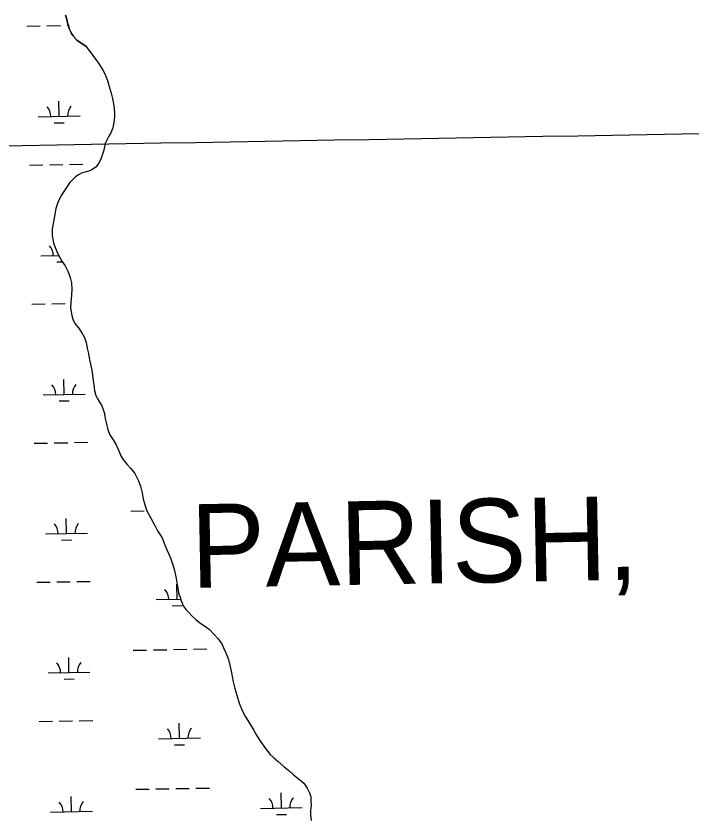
# Model space of a CAD drawing. Extents: x 3903937 to 3942190, y 260677 to 286651.
# Drawn here: x 3915954 to 3917570, y 276665 to 278583 of the extents above; entities that cross this region are included whole.
import ezdxf

# ---------------------------------------------------------------- set-up
doc = ezdxf.new("R2010")
doc.units = 0
for name, color, linetype in [('V-GRID-MAJR', 7, 'Continuous'), ('V-TOPO-GNAM-IDEN', 7, 'Continuous'), ('V-TOPO-SHOR', 7, 'Continuous'), ('V-WETL-SWMP', 7, 'Continuous')]:
    doc.layers.add(name, color=color, linetype=linetype)

msp = doc.modelspace()

# ---------------------------------------------------------------- linework, layer by layer
at = {"layer": 'V-GRID-MAJR'}
msp.add_spline([(3907996.24, 278136.142), (3913310.651, 278227.748), (3918625.049, 278320.127), (3923939.434, 278413.279), (3929253.805, 278507.203), (3934568.162, 278601.901), (3939882.505, 278697.37200000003), (3939882.506, 278697.37200000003)], degree=3, dxfattribs=at)
at = {"layer": 'V-TOPO-SHOR'}
for points in [[(3916121.0300000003, 278510.66000000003), (3916098.768, 278525.893), (3916095.019, 278529.926), (3916093.075, 278532.551), (3916090.083, 278536.266), (3916086.3540000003, 278541.67100000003), (3916083.544, 278547.213), (3916081.045, 278553.21), (3916078.717, 278560.271), (3916077.269, 278565.029), (3916075.835, 278570.853), (3916073.971, 278578.214), (3916071.952, 278585.574)], [(3916121.0300000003, 278510.66000000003), (3916151.115, 278470.827), (3916162.9450000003, 278451.279), (3916167.4560000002, 278441.29), (3916171.9930000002, 278428.896), (3916176.5470000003, 278414.492), (3916181.119, 278398.487), (3916184.049, 278386.074), (3916186.583, 278373.25800000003), (3916188.301, 278361.64), (3916189.204, 278351.213), (3916189.3000000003, 278341.58400000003), (3916187.816, 278329.13), (3916184.731, 278316.25800000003), (3916180.035, 278304.175), (3916175.704, 278295.704), (3916167.045, 278278.364), (3916163.592, 278262.279), (3916159.696, 278250.202), (3916156.1720000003, 278241.34), (3916150.6610000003, 278230.451), (3916145.1210000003, 278222.37200000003), (3916135.157, 278215.451), (3916127.967, 278212.17), (3916119.162, 278209.676), (3916111.9560000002, 278208.001), (3916103.1720000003, 278203.501), (3916095.594, 278198.613), (3916082.487, 278184.84), (3916072.593, 278170.69800000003), (3916061.519, 278154.136), (3916053.659, 278137.206), (3916048.986, 278122.714), (3916045.5470000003, 278105.023), (3916042.5100000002, 278087.337), (3916040.241, 278073.26900000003), (3916040.392, 278057.62), (3916042.96, 278041.193), (3916047.083, 278029.999), (3916053.653, 278014.813), (3916063.457, 277997.253), (3916071.188, 277986.092), (3916077.3340000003, 277973.31), (3916083.103, 277957.719), (3916086.038, 277944.904), (3916086.995, 277929.266), (3916086.321, 277916.015), (3916084.48, 277899.14400000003), (3916083.812, 277885.494), (3916087.205, 277866.667), (3916089.6920000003, 277858.665), (3916094.609, 277848.28), (3916103.1410000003, 277837.528), (3916111.284, 277825.57), (3916117.0100000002, 277814.39), (3916121.139, 277802.792), (3916124.08, 277789.177), (3916127.015, 277776.364), (3916129.5700000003, 277761.142), (3916131.68, 277750.727), (3916134.629, 277736.31200000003), (3916141.123, 277687.819), (3916144.455, 277675.412), (3916147.327, 277669.018), (3916153.034, 277659.84500000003), (3916157.9250000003, 277652.27), (3916162.039, 277641.876), (3916164.937, 277632.675), (3916165.822, 277624.255), (3916168.757, 277611.445), (3916172.943, 277593.828), (3916177.875, 277581.837), (3916185.616, 277569.875), (3916192.96, 277557.507), (3916199.522, 277543.126), (3916204.0500000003, 277531.532), (3916210.573, 277521.163), (3916219.105, 277510.411), (3916228.026, 277500.867), (3916237.3710000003, 277488.92100000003), (3916245.952, 277473.354), (3916250.912, 277458.556), (3916255.08, 277442.544), (3916257.22, 277428.92100000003), (3916261.376, 277414.515), (3916266.733, 277400.12200000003), (3916274.919, 277383.75), (3916285.134, 277364.989), (3916292.085, 277351.816), (3916303.079, 277335.471), (3916310.491, 277316.281), (3916315.019, 277304.68700000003), (3916323.213, 277287.513), (3916328.188, 277271.108), (3916332.339, 277257.104), (3916336.134, 277238.281), (3916339.089, 277223.462), (3916342.927, 277200.225), (3916345.806, 277193.03), (3916348.698, 277184.632), (3916354.035, 277172.243)], [(3916354.035, 277172.243), (3916359.733, 277164.27400000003), (3916365.8170000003, 277157.512), (3916374.7430000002, 277147.567), (3916383.645, 277140.03), (3916392.951, 277132.094), (3916406.681, 277123.4), (3916416.381, 277116.273), (3916426.924, 277105.14), (3916436.664, 277093.999), (3916445.614, 277081.648), (3916450.537, 277070.46), (3916455.055, 277060.07), (3916461.23, 277044.079), (3916464.969, 277030.874), (3916467.9250000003, 277016.055), (3916472.987, 276990.82300000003), (3916476.3540000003, 276974.806), (3916481.327, 276958.803), (3916487.133, 276939.597), (3916494.127, 276922.00800000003), (3916502.3000000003, 276906.841), (3916511.674, 276892.085), (3916521.461, 276876.129), (3916529.627, 276861.762), (3916538.187, 276848.202), (3916549.992, 276831.063), (3916561.365, 276817.128), (3916569.464, 276809.583), (3916579.987, 276800.457), (3916594.96, 276787.762), (3916605.481, 276778.636), (3916617.22, 276768.316), (3916632.18, 276756.827), (3916641.8880000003, 276748.897), (3916649.629, 276736.933), (3916655.362, 276725.351), (3916658.2600000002, 276716.15), (3916658.7630000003, 276705.721), (3916658.858, 276696.091), (3916657.7800000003, 276683.24), (3916657.481, 276672.804), (3916659.218, 276659.176)]]:
    msp.add_lwpolyline(points, dxfattribs=at)
at = {"layer": 'V-WETL-SWMP'}
for p, q in [((3916071.953, 278585.5749999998), (3916073.971, 278578.21299999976)), ((3916073.971, 278578.21299999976), (3916075.836, 278570.85299999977)), ((3916075.836, 278570.85299999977), (3916077.268, 278565.028)), ((3916077.268, 278565.028), (3916078.717, 278560.2709999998)), ((3915979.6389084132, 278559.3697548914), (3916011.63395243, 278559.93292306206)), ((3916027.6314744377, 278560.2145071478), (3916059.6265184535, 278560.7776753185)), ((3916075.624040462, 278561.0592594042), (3916078.4616790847, 278561.1092067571)), ((3916078.717, 278560.2709999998), (3916081.045, 278553.20900000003)), ((3916081.045, 278553.20900000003), (3916083.543, 278547.213)), ((3916083.543, 278547.213), (3916086.353, 278541.67100000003)), ((3916086.353, 278541.67100000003), (3916090.082, 278536.266)), ((3916090.082, 278536.26599999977), (3916093.076, 278532.552)), ((3916093.076, 278532.552), (3916095.018, 278529.92499999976)), ((3916095.018, 278529.92499999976), (3916098.769, 278525.89399999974)), ((3916098.769, 278525.89399999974), (3916121.031, 278510.66000000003)), ((3916121.031, 278510.66000000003), (3916151.116, 278470.826)), ((3916151.116, 278470.826), (3916162.9450000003, 278451.27799999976)), ((3916162.9450000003, 278451.27799999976), (3916167.457, 278441.29)), ((3916167.457, 278441.29), (3916171.992, 278428.895)), ((3916171.992, 278428.895), (3916176.5470000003, 278414.4929999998)), ((3916176.5470000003, 278414.4929999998), (3916181.1180000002, 278398.487)), ((3916181.1180000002, 278398.487), (3916184.049, 278386.0749999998)), ((3916056.8588001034, 278343.4523080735), (3916056.2252359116, 278379.4467325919)), ((3916184.049, 278386.0749999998), (3916186.582, 278373.259)), ((3916186.582, 278373.259), (3916188.301, 278361.639)), ((3916188.301, 278361.639), (3916189.205, 278351.214)), ((3916006.866543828, 278342.57235780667), (3916106.8510563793, 278344.3322583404)), ((3916189.3000000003, 278341.58400000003), (3916187.816, 278329.13)), ((3916189.205, 278351.214), (3916189.3000000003, 278341.58400000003)), ((3916045.1322288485, 278327.81250987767), (3916069.128511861, 278328.2348860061)), ((3916184.7320000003, 278316.25800000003), (3916180.035, 278304.174)), ((3916187.816, 278329.13), (3916184.7320000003, 278316.25800000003)), ((3916175.704, 278295.704), (3916167.045, 278278.36399999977)), ((3916180.035, 278304.174), (3916175.704, 278295.704)), ((3916167.045, 278278.36399999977), (3916163.591, 278262.279)), ((3916163.591, 278262.279), (3916159.696, 278250.202)), ((3916156.171, 278241.34), (3916150.66, 278230.451)), ((3916159.696, 278250.202), (3916156.171, 278241.34)), ((3915985.4936575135, 278226.7462777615), (3916017.4887015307, 278227.30944593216)), ((3916033.4862235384, 278227.5910300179), (3916065.4812675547, 278228.15419818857)), ((3916081.4787895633, 278228.43578227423), (3916113.473833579, 278228.9989504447)), ((3916145.1210000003, 278222.371), (3916135.157, 278215.45199999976)), ((3916150.66, 278230.451), (3916145.1210000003, 278222.371)), ((3916103.171, 278203.501), (3916095.594, 278198.6119999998)), ((3916111.955, 278208.00099999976), (3916103.171, 278203.501)), ((3916119.162, 278209.677), (3916111.955, 278208.00099999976)), ((3916127.966, 278212.17099999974), (3916119.162, 278209.677)), ((3916135.157, 278215.45199999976), (3916127.966, 278212.17099999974)), ((3916082.486, 278184.8399999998), (3916072.593, 278170.69800000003)), ((3916095.594, 278198.6119999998), (3916082.486, 278184.8399999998)), ((3916072.593, 278170.69800000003), (3916061.519, 278154.137)), ((3916061.519, 278154.137), (3916053.659, 278137.206)), ((3916053.659, 278137.206), (3916048.985, 278122.714)), ((3916045.5470000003, 278105.023), (3916042.5100000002, 278087.33699999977)), ((3916048.985, 278122.714), (3916045.5470000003, 278105.023)), ((3916042.5100000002, 278087.33699999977), (3916040.24, 278073.27)), ((3916040.24, 278073.27), (3916040.393, 278057.621)), ((3916040.393, 278057.621), (3916042.961, 278041.1939999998)), ((3916042.961, 278041.1939999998), (3916047.0840000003, 278029.998)), ((3916047.0840000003, 278029.998), (3916053.653, 278014.813)), ((3916012.721292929, 278009.94888067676), (3916055.943714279, 278010.70967012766)), ((3916053.653, 278014.813), (3916063.4560000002, 277997.2529999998)), ((3916050.9869779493, 277995.18903274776), (3916064.7185744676, 277995.43073262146)), ((3916063.4560000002, 277997.2529999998), (3916071.1890000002, 277986.092)), ((3916071.1890000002, 277986.092), (3916077.3340000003, 277973.31099999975)), ((3916077.3340000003, 277973.31099999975), (3916083.1040000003, 277957.718)), ((3916083.1040000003, 277957.718), (3916086.039, 277944.9049999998)), ((3916086.039, 277944.9049999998), (3916086.994, 277929.2649999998)), ((3916086.321, 277916.016), (3916084.48, 277899.14400000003)), ((3916086.994, 277929.2649999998), (3916086.321, 277916.016)), ((3915991.3484066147, 277894.1228006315), (3916023.343450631, 277894.6859688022)), ((3916039.340972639, 277894.9675528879), (3916071.336016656, 277895.5307210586)), ((3916084.48, 277899.14400000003), (3916083.811, 277885.493)), ((3916083.811, 277885.493), (3916087.2060000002, 277866.666)), ((3916087.2060000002, 277866.666), (3916089.6920000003, 277858.66499999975)), ((3916089.6920000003, 277858.66499999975), (3916094.609, 277848.27899999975)), ((3916094.609, 277848.27899999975), (3916103.1410000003, 277837.528)), ((3916103.1410000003, 277837.528), (3916111.284, 277825.569)), ((3916111.284, 277825.569), (3916117.011, 277814.389)), ((3916117.011, 277814.389), (3916121.1380000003, 277802.792)), ((3916121.1380000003, 277802.792), (3916124.08, 277789.177)), ((3916124.08, 277789.177), (3916127.014, 277776.365)), ((3916127.014, 277776.365), (3916129.571, 277761.14099999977)), ((3916129.571, 277761.14099999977), (3916131.679, 277750.72799999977)), ((3916131.679, 277750.72799999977), (3916134.629, 277736.31099999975)), ((3916134.629, 277736.31099999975), (3916141.123, 277687.8189999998)), ((3916068.568298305, 277678.20535381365), (3916067.934734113, 277714.199778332)), ((3916141.123, 277687.8189999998), (3916144.455, 277675.4119999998)), ((3916018.5760420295, 277677.3254035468), (3916118.5605545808, 277679.0853040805)), ((3916056.8417270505, 277662.5655556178), (3916080.8380100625, 277662.98793174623)), ((3916144.455, 277675.4119999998), (3916147.327, 277669.01899999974)), ((3916147.327, 277669.01899999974), (3916153.034, 277659.84500000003)), ((3916153.034, 277659.84500000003), (3916157.924, 277652.26899999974)), ((3916157.924, 277652.26899999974), (3916162.039, 277641.87599999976)), ((3916162.039, 277641.87599999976), (3916164.938, 277632.675)), ((3916164.938, 277632.675), (3916165.823, 277624.256)), ((3916165.823, 277624.256), (3916168.757, 277611.4439999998)), ((3916168.757, 277611.4439999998), (3916172.9420000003, 277593.828)), ((3916172.9420000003, 277593.828), (3916177.875, 277581.83799999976)), ((3916177.875, 277581.83799999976), (3916185.617, 277569.875)), ((3916185.617, 277569.875), (3916192.961, 277557.507)), ((3915997.203155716, 277561.49932350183), (3916029.1981997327, 277562.0624916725)), ((3916045.195721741, 277562.34407575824), (3916077.1907657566, 277562.90724392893)), ((3916093.1882877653, 277563.1888280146), (3916125.1833317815, 277563.75199618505)), ((3916192.961, 277557.507), (3916199.522, 277543.12499999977)), ((3916199.522, 277543.12499999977), (3916204.0500000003, 277531.5319999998)), ((3916204.0500000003, 277531.5319999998), (3916210.572, 277521.1619999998)), ((3916210.572, 277521.1619999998), (3916219.1040000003, 277510.411)), ((3916219.1040000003, 277510.411), (3916228.026, 277500.868)), ((3916228.026, 277500.868), (3916237.372, 277488.92100000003)), ((3916237.372, 277488.92100000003), (3916245.952, 277473.354)), ((3916245.952, 277473.354), (3916250.912, 277458.555)), ((3916250.912, 277458.555), (3916255.0810000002, 277442.54499999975)), ((3916255.0810000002, 277442.54499999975), (3916257.221, 277428.9219999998)), ((3916257.221, 277428.9219999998), (3916261.375, 277414.516)), ((3916261.375, 277414.516), (3916266.733, 277400.12200000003)), ((3916228.098096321, 277399.03668347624), (3916260.093140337, 277399.5998516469)), ((3916266.733, 277400.12200000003), (3916274.919, 277383.74999999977)), ((3916074.423047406, 277345.581876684), (3916073.7894832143, 277381.5763012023)), ((3916274.919, 277383.74999999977), (3916285.134, 277364.98899999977)), ((3916285.134, 277364.98899999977), (3916292.085, 277351.815)), ((3916024.430791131, 277344.7019264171), (3916124.4153036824, 277346.4618269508)), ((3916292.085, 277351.815), (3916303.08, 277335.46999999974)), ((3916062.6964761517, 277329.9420784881), (3916086.692759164, 277330.36445461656)), ((3916303.08, 277335.46999999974), (3916310.491, 277316.281)), ((3916310.491, 277316.281), (3916315.018, 277304.688)), ((3916315.018, 277304.688), (3916323.2120000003, 277287.51299999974)), ((3916323.2120000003, 277287.51299999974), (3916328.188, 277271.109)), ((3916328.188, 277271.109), (3916332.338, 277257.10399999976)), ((3916332.338, 277257.10399999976), (3916336.134, 277238.281)), ((3916003.0579048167, 277228.87584637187), (3916035.0529488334, 277229.43901454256)), ((3916051.0504708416, 277229.7205986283), (3916083.045514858, 277230.28376679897)), ((3916099.0430368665, 277230.5653508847), (3916131.0380808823, 277231.12851905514)), ((3916336.134, 277238.281), (3916339.088, 277223.46199999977)), ((3916338.667167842, 277188.34595853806), (3916338.0336036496, 277224.34038305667)), ((3916339.088, 277223.46199999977), (3916342.927, 277200.22499999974)), ((3916288.674911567, 277187.466008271), (3916347.366303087, 277188.4990783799)), ((3916342.927, 277200.22499999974), (3916345.806, 277193.0299999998)), ((3916345.806, 277193.0299999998), (3916348.698, 277184.63199999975)), ((3916348.698, 277184.63199999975), (3916354.0360000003, 277172.244)), ((3916326.9405965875, 277172.7061603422), (3916350.936879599, 277173.1285364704)), ((3916354.0360000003, 277172.244), (3916359.7320000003, 277164.27400000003)), ((3916359.7320000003, 277164.27400000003), (3916365.8170000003, 277157.51199999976)), ((3916365.8170000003, 277157.51199999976), (3916374.7430000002, 277147.567)), ((3916374.7430000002, 277147.567), (3916383.645, 277140.03)), ((3916383.645, 277140.03), (3916392.952, 277132.09499999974)), ((3916392.952, 277132.09499999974), (3916406.681, 277123.401)), ((3916406.681, 277123.401), (3916416.381, 277116.27299999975)), ((3916416.381, 277116.27299999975), (3916426.924, 277105.1399999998)), ((3916426.924, 277105.14), (3916436.664, 277093.999)), ((3916436.664, 277093.999), (3916445.613, 277081.64699999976)), ((3916329.937977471, 277068.10271085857), (3916361.933021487, 277068.6658790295)), ((3916377.9305434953, 277068.947463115), (3916409.925587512, 277069.51063128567)), ((3916445.613, 277081.64699999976), (3916450.538, 277070.45899999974)), ((3916450.538, 277070.45899999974), (3916455.054, 277060.07)), ((3916080.277796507, 277012.958399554), (3916079.644232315, 277048.9528240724)), ((3916233.952845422, 277066.4132063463), (3916265.947889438, 277066.97637451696)), ((3916281.9454114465, 277067.2579586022), (3916313.9404554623, 277067.8211267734)), ((3916455.054, 277060.07), (3916461.23, 277044.0789999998)), ((3916461.23, 277044.0789999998), (3916464.97, 277030.873)), ((3916464.97, 277030.873), (3916467.924, 277016.054)), ((3916030.285540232, 277012.07844928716), (3916130.270052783, 277013.8383498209)), ((3916467.924, 277016.054), (3916472.987, 276990.82300000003)), ((3916068.5512252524, 276997.31860135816), (3916092.5475082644, 276997.7409774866)), ((3916472.987, 276990.82300000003), (3916476.3540000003, 276974.80499999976)), ((3916476.3540000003, 276974.80499999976), (3916481.326, 276958.802)), ((3916481.326, 276958.802), (3916487.132, 276939.597)), ((3916487.132, 276939.597), (3916494.126, 276922.009)), ((3916494.126, 276922.009), (3916502.3000000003, 276906.8399999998)), ((3916008.912653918, 276896.25236924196), (3916040.907697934, 276896.81553741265)), ((3916056.9052199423, 276897.0971214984), (3916088.900263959, 276897.66028966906)), ((3916104.8977859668, 276897.9418737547), (3916136.8928299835, 276898.5050419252)), ((3916502.3000000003, 276906.8399999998), (3916511.674, 276892.08399999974)), ((3916344.5219169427, 276855.7224814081), (3916343.888352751, 276891.7169059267)), ((3916511.674, 276892.08399999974), (3916521.461, 276876.1279999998)), ((3916521.461, 276876.1279999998), (3916529.627, 276861.76199999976)), ((3916529.627, 276861.76199999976), (3916538.187, 276848.20199999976)), ((3916294.5296606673, 276854.84253114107), (3916394.514173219, 276856.6024316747)), ((3916332.795345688, 276840.0826832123), (3916356.7916287, 276840.5050593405)), ((3916538.187, 276848.202), (3916549.992, 276831.06199999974)), ((3916549.992, 276831.06199999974), (3916561.365, 276817.129)), ((3916561.365, 276817.129), (3916569.464, 276809.583)), ((3916569.464, 276809.583), (3916579.987, 276800.457)), ((3916579.987, 276800.457), (3916594.9590000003, 276787.762)), ((3916594.9590000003, 276787.762), (3916605.481, 276778.63599999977)), ((3916605.481, 276778.63599999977), (3916617.22, 276768.31699999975)), ((3916617.22, 276768.31699999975), (3916632.18, 276756.82599999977)), ((3916632.18, 276756.82599999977), (3916641.8880000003, 276748.8959999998)), ((3916641.8880000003, 276748.896), (3916649.63, 276736.9329999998)), ((3916239.8075945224, 276733.78972921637), (3916271.802638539, 276734.35289738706)), ((3916287.8001605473, 276734.63448147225), (3916319.7952045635, 276735.1976496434)), ((3916335.792726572, 276735.47923372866), (3916367.787770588, 276736.0424018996)), ((3916383.7852925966, 276736.3239859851), (3916415.780336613, 276736.88715415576)), ((3916587.9628128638, 276689.16800399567), (3916587.3292486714, 276725.162428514)), ((3916649.63, 276736.9329999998), (3916655.361, 276725.3519999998)), ((3916655.361, 276725.3519999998), (3916658.2600000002, 276716.15)), ((3916086.132545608, 276680.3349224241), (3916085.4989814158, 276716.3293469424)), ((3916658.2600000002, 276716.15), (3916658.764, 276705.722)), ((3916658.764, 276705.722), (3916658.858, 276696.0919999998)), ((3916537.9705565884, 276688.2880537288), (3916637.9550691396, 276690.0479542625)), ((3916658.858, 276696.0919999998), (3916657.7800000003, 276683.23999999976)), ((3916036.1402893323, 276679.45497215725), (3916136.124801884, 276681.2148726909)), ((3916576.2362416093, 276673.5282057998), (3916600.2325246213, 276673.95058192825)), ((3916657.7800000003, 276683.23999999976), (3916657.481, 276672.80399999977)), ((3916657.481, 276672.80399999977), (3916659.219, 276659.1769999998))]:
    msp.add_line(p, q, dxfattribs=at)
for centre, radius, start, end in [((3916001.6160636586, 278342.95481699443), 35.24628790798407, 0.23658072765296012, 41.78023906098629), ((3916112.0848244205, 278344.8992584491), 35.24628790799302, 140.23657772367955, 181.78023605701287), ((3916007.4708127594, 278010.3313398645), 35.24628790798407, 0.23658072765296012, 41.78023906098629), ((3916013.32556186, 277677.70786273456), 35.24628790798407, 0.23658072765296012, 41.78023906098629), ((3916123.7943226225, 277679.6523041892), 35.24628790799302, 140.23657772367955, 181.78023605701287), ((3916019.180310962, 277345.0843856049), 35.24628790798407, 0.23658072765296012, 41.78023906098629), ((3916129.6490717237, 277347.0288270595), 35.24628790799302, 140.23657772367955, 181.78023605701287), ((3916283.4244313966, 277187.84846745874), 35.24628790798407, 0.23658072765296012, 41.78023906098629), ((3916025.0350600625, 277012.4609084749), 35.24628790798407, 0.23658072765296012, 41.78023906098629), ((3916135.503820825, 277014.4053499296), 35.24628790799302, 140.23657772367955, 181.78023605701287), ((3916289.279180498, 276855.2249903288), 35.24628790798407, 0.23658072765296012, 41.78023906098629), ((3916399.7479412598, 276857.16943178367), 35.24628790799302, 140.23657772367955, 181.78023605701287), ((3916141.358569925, 276681.7818727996), 35.24628790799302, 140.23657772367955, 181.78023605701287), ((3916532.720076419, 276688.6705129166), 35.24628790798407, 0.23658072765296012, 41.78023906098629), ((3916643.1888371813, 276690.61495437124), 35.24628790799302, 140.23657772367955, 181.78023605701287), ((3916030.8898091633, 276679.837431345), 35.24628790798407, 0.23658072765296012, 41.78023906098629)]:
    msp.add_arc(centre, radius, start, end, dxfattribs=at)

# ---------------------------------------------------------------- texts
at = {"layer": 'V-TOPO-GNAM-IDEN'}
msp.add_text('PARISH,', height=199.99959800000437, rotation=1.0871194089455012, dxfattribs=at).set_placement((3916372.739317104, 277215.36255276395))

doc.saveas('drawing.dxf')
